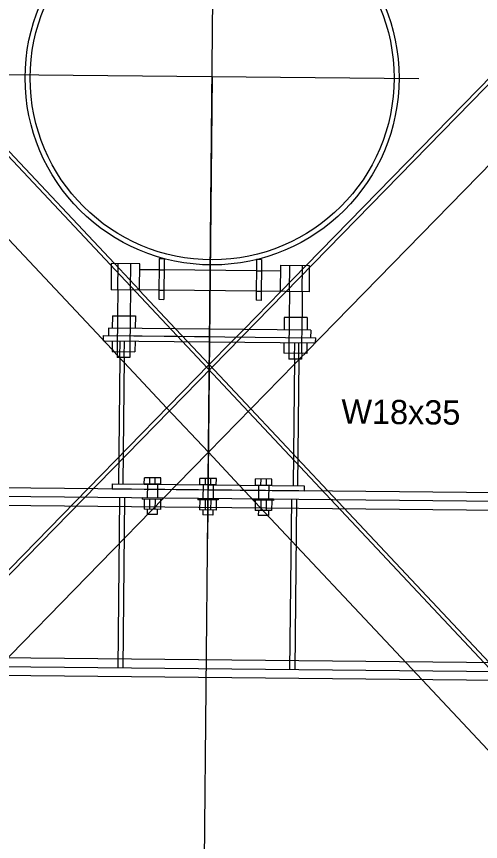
# Model space of a CAD drawing. Extents: x 632312 to 632425, y 378332 to 378413.
# Drawn here: x 632344.74 to 632348.57, y 378386.07 to 378392.88 of the extents above; entities that cross this region are included whole.
import ezdxf

# ---------------------------------------------------------------- set-up
doc = ezdxf.new("R2010")
doc.units = 0
for name, color, linetype in [('B_Boring', 7, 'Continuous'), ('R_Proposed Const Limits Cut', 7, 'Continuous'), ('R_Road Edge of Shoulder', 7, 'Continuous'), ('SHT_Dimensions', 7, 'Continuous')]:
    doc.layers.add(name, color=color, linetype=linetype)

msp = doc.modelspace()

# ---------------------------------------------------------------- linework, layer by layer
at = {"layer": 'B_Boring'}
for p, q in [((632345.9195, 378390.881), (632345.9162, 378390.5452)), ((632345.9195, 378390.881), (632345.9606, 378390.8806)), ((632345.9606, 378390.8806), (632345.9573, 378390.5448)), ((632346.7211, 378390.873), (632346.7178, 378390.5372)), ((632346.7622, 378390.8726), (632346.7211, 378390.873)), ((632346.7622, 378390.8726), (632346.7588, 378390.5368)), ((632345.5242, 378390.8408), (632345.522, 378390.624)), ((632345.7583, 378390.8385), (632345.5242, 378390.8408)), ((632345.7561, 378390.6217), (632345.7583, 378390.8385)), ((632345.9186, 378390.7881), (632345.7578, 378390.7897)), ((632346.7202, 378390.7801), (632345.9597, 378390.7877)), ((632346.922, 378390.7781), (632346.7612, 378390.7797)), ((632346.9204, 378390.6101), (632346.9225, 378390.8269)), ((632346.9225, 378390.8269), (632347.1566, 378390.8246)), ((632347.1566, 378390.8246), (632347.1545, 378390.6078)), ((632345.9169, 378390.6201), (632345.522, 378390.624)), ((632345.5776, 378390.6235), (632345.5754, 378390.41)), ((632345.6824, 378390.6224), (632345.6802, 378390.4089)), ((632346.7185, 378390.6121), (632345.958, 378390.6197)), ((632347.1545, 378390.6078), (632346.7596, 378390.6117)), ((632346.9942, 378390.6094), (632346.992, 378390.3959)), ((632347.0989, 378390.6083), (632347.0968, 378390.3949)), ((632345.9162, 378390.5452), (632345.9573, 378390.5448)), ((632346.7588, 378390.5368), (632346.7178, 378390.5372)), ((632345.5332, 378390.4104), (632345.5322, 378390.3083)), ((632345.5332, 378390.4104), (632345.7224, 378390.4085)), ((632345.7224, 378390.4085), (632345.7214, 378390.3064)), ((632346.9498, 378390.3963), (632346.9488, 378390.2942)), ((632347.139, 378390.3944), (632346.9498, 378390.3963)), ((632347.139, 378390.3944), (632347.138, 378390.2923)), ((632345.5018, 378390.3086), (632345.5012, 378390.2454)), ((632347.1684, 378390.292), (632345.5018, 378390.3086)), ((632345.4591, 378390.2041), (632345.4595, 378390.2458)), ((632345.4595, 378390.2458), (632347.2094, 378390.2284)), ((632347.1684, 378390.292), (632347.1678, 378390.2288)), ((632345.4591, 378390.2041), (632347.209, 378390.1867)), ((632345.5312, 378390.2034), (632345.5303, 378390.1154)), ((632345.7204, 378390.2015), (632345.7195, 378390.1135)), ((632346.9478, 378390.1893), (632346.9469, 378390.1013)), ((632347.137, 378390.1874), (632347.1361, 378390.0994)), ((632347.209, 378390.1867), (632347.2094, 378390.2284)), ((632345.5303, 378390.1154), (632345.7195, 378390.1135)), ((632345.5725, 378390.115), (632345.572, 378390.0659)), ((632345.6773, 378390.1139), (632345.6768, 378390.0649)), ((632347.1361, 378390.0994), (632346.9469, 378390.1013)), ((632346.9891, 378390.1009), (632346.9886, 378390.0519)), ((632347.0939, 378390.0998), (632347.0934, 378390.0508)), ((632345.6768, 378390.0649), (632345.572, 378390.0659)), ((632345.5952, 378390.0657), (632345.5849, 378389.0232)), ((632345.6307, 378390.0654), (632345.6203, 378389.0228)), ((632347.0934, 378390.0508), (632346.9886, 378390.0519)), ((632347.0348, 378390.0514), (632347.0244, 378389.0089)), ((632347.0702, 378390.051), (632347.0598, 378389.0085)), ((632345.7963, 378389.0211), (632345.7969, 378389.0732)), ((632345.9322, 378389.0718), (632345.7969, 378389.0732)), ((632345.8415, 378389.0206), (632345.842, 378389.0727)), ((632351.8217, 378388.9195), (632340.8222, 378389.0289)), ((632345.5307, 378389.0237), (632345.5303, 378388.982)), ((632345.5307, 378389.0237), (632347.114, 378389.008)), ((632345.9317, 378389.0197), (632345.7963, 378389.0211)), ((632345.8224, 378389.0208), (632345.8212, 378388.9067)), ((632345.8866, 378389.0202), (632345.8871, 378389.0723)), ((632345.9057, 378389.02), (632345.9046, 378388.9058)), ((632345.9317, 378389.0197), (632345.9322, 378389.0718)), ((632346.2546, 378389.0165), (632346.2552, 378389.0686)), ((632346.39, 378389.0152), (632346.2546, 378389.0165)), ((632346.3906, 378389.0673), (632346.2552, 378389.0686)), ((632346.2807, 378389.0163), (632346.2795, 378388.9021)), ((632346.2998, 378389.0161), (632346.3003, 378389.0682)), ((632346.3449, 378389.0156), (632346.3454, 378389.0677)), ((632346.364, 378389.0155), (632346.3629, 378388.9013)), ((632346.39, 378389.0152), (632346.3906, 378389.0673)), ((632346.713, 378389.012), (632346.7135, 378389.0641)), ((632346.8484, 378389.0106), (632346.713, 378389.012)), ((632346.8489, 378389.0627), (632346.7135, 378389.0641)), ((632346.739, 378389.0117), (632346.7379, 378388.8976)), ((632346.7581, 378389.0115), (632346.7586, 378389.0636)), ((632346.8032, 378389.0111), (632346.8037, 378389.0632)), ((632346.8223, 378389.0109), (632346.8212, 378388.8967)), ((632346.8484, 378389.0106), (632346.8489, 378389.0627)), ((632347.114, 378389.008), (632347.1135, 378388.9663)), ((632351.8209, 378388.847), (632340.8215, 378388.9564)), ((632345.5303, 378388.9821), (632347.1135, 378388.9663)), ((632345.5921, 378388.909), (632345.5781, 378387.504)), ((632345.6337, 378388.9085), (632345.6198, 378387.5036)), ((632345.7796, 378388.9071), (632345.7795, 378388.8967)), ((632345.9461, 378388.895), (632345.7795, 378388.8967)), ((632345.9462, 378388.9054), (632345.7796, 378388.9071)), ((632345.7951, 378388.8965), (632345.7943, 378388.8132)), ((632345.8402, 378388.8961), (632345.8394, 378388.8127)), ((632345.8854, 378388.8956), (632345.8845, 378388.8123)), ((632345.9305, 378388.8952), (632345.9297, 378388.8118)), ((632345.9462, 378388.9054), (632345.9461, 378388.895)), ((632346.2379, 378388.9025), (632346.2378, 378388.8921)), ((632346.4044, 378388.8905), (632346.2378, 378388.8921)), ((632346.4045, 378388.9009), (632346.2379, 378388.9025)), ((632346.2534, 378388.892), (632346.2526, 378388.8086)), ((632346.2985, 378388.8915), (632346.2977, 378388.8082)), ((632346.3437, 378388.8911), (632346.3428, 378388.8077)), ((632346.3888, 378388.8906), (632346.388, 378388.8073)), ((632346.4045, 378388.9009), (632346.4044, 378388.8905)), ((632346.6962, 378388.898), (632346.6961, 378388.8876)), ((632346.8627, 378388.8859), (632346.6961, 378388.8876)), ((632346.8628, 378388.8963), (632346.6962, 378388.898)), ((632346.7117, 378388.8874), (632346.7109, 378388.8041)), ((632346.7568, 378388.887), (632346.756, 378388.8036)), ((632346.802, 378388.8865), (632346.8012, 378388.8032)), ((632346.8471, 378388.8861), (632346.8463, 378388.8027)), ((632346.8628, 378388.8963), (632346.8627, 378388.8859)), ((632347.0087, 378388.8949), (632346.9947, 378387.4899)), ((632347.0503, 378388.8945), (632347.0364, 378387.4895)), ((632345.9297, 378388.8118), (632345.7943, 378388.8132)), ((632345.8203, 378388.8129), (632345.8199, 378388.7713)), ((632345.9036, 378388.8121), (632345.9032, 378388.7704)), ((632346.388, 378388.8073), (632346.2526, 378388.8086)), ((632346.2786, 378388.8084), (632346.2782, 378388.7667)), ((632346.3619, 378388.8075), (632346.3615, 378388.7659)), ((632346.8463, 378388.8027), (632346.7109, 378388.8041)), ((632346.7369, 378388.8038), (632346.7365, 378388.7622)), ((632346.8203, 378388.803), (632346.8198, 378388.7613)), ((632345.9032, 378388.7704), (632345.8199, 378388.7713)), ((632346.3615, 378388.7659), (632346.2782, 378388.7667)), ((632346.8198, 378388.7613), (632346.7365, 378388.7622)), ((632351.807, 378387.4421), (632340.8075, 378387.5515)), ((632351.8062, 378387.3696), (632340.8068, 378387.479))]:
    msp.add_line(p, q, dxfattribs=at)
for points in [[(632347.1362, 378390.1143), (632350.9136, 378393.9818), (632350.5559, 378394.3312), (632347.1313, 378390.8248)], [(632344.6417, 378391.8078), (632345.5495, 378390.8406)], [(632345.5305, 378390.1302), (632344.6345, 378391.0849)], [(632345.7549, 378390.6217), (632346.054, 378390.3031)], [(632346.9216, 378390.6101), (632346.6163, 378390.2975)], [(632346.5148, 378390.1936), (632346.3322, 378390.0067), (632345.3334, 378388.984)], [(632346.1533, 378390.1972), (632346.3322, 378390.0067)], [(632345.5722, 378390.0858), (632345.5446, 378390.1152)], [(632347.0936, 378390.0706), (632347.1218, 378390.0995)], [(632345.5952, 378390.0613), (632345.591, 378390.0657)], [(632347.0701, 378390.0466), (632347.0744, 378390.051)], [(632345.9825, 378389.6486), (632345.6302, 378390.0239)], [(632346.0659, 378389.0184), (632346.325, 378389.2837), (632347.0343, 378390.01)], [(632346.6747, 378389.6417), (632347.3104, 378388.9644)], [(632346.5788, 378389.0133), (632346.325, 378389.2837)], [(632350.4619, 378384.876), (632348.0868, 378387.4066)]]:
    msp.add_lwpolyline(points, dxfattribs=at)
for radius in [1.5417, 1.5]:
    msp.add_circle((632346.3557, 378392.3708), radius, dxfattribs=at)
at = {"layer": 'R_Proposed Const Limits Cut'}
for p, q in [((632342.1725, 378394.3929), (632350.8037, 378385.1968)), ((632350.5783, 378394.3094), (632341.7659, 378385.2867)), ((632345.7561, 378390.6217), (632345.5495, 378390.8406)), ((632345.5776, 378390.6235), (632345.5797, 378390.8403)), ((632345.6824, 378390.6224), (632345.6845, 378390.8392)), ((632345.9186, 378390.7881), (632345.9597, 378390.7877)), ((632346.7202, 378390.7801), (632346.7612, 378390.7797)), ((632346.9216, 378390.6101), (632347.1313, 378390.8248)), ((632346.9942, 378390.6094), (632346.9963, 378390.8262)), ((632347.0989, 378390.6083), (632347.1011, 378390.8251)), ((632345.9169, 378390.6201), (632345.958, 378390.6197)), ((632346.7185, 378390.6121), (632346.7596, 378390.6117)), ((632345.5754, 378390.41), (632345.5725, 378390.115)), ((632345.6802, 378390.4089), (632345.6773, 378390.1139)), ((632346.992, 378390.3959), (632346.9891, 378390.1009)), ((632347.0939, 378390.0998), (632347.0968, 378390.3949)), ((632346.1533, 378390.1972), (632346.054, 378390.3031)), ((632346.5148, 378390.1936), (632346.6163, 378390.2975)), ((632345.5952, 378390.0657), (632345.5966, 378390.2028)), ((632345.6307, 378390.0654), (632345.632, 378390.2024)), ((632347.0348, 378390.0514), (632347.0361, 378390.1884)), ((632347.0702, 378390.051), (632347.0715, 378390.1881)), ((632345.5305, 378390.1302), (632345.5446, 378390.1152)), ((632347.1218, 378390.0995), (632347.1362, 378390.1143)), ((632345.5722, 378390.0858), (632345.591, 378390.0657)), ((632345.5952, 378390.0613), (632345.6302, 378390.0239)), ((632347.0343, 378390.01), (632347.0701, 378390.0466)), ((632347.0744, 378390.051), (632347.0936, 378390.0706)), ((632346.6747, 378389.6417), (632346.3322, 378390.0067)), ((632345.9825, 378389.6486), (632346.325, 378389.2837)), ((632344.5262, 378387.442), (632346.0659, 378389.0184)), ((632346.5788, 378389.0133), (632348.0868, 378387.4066)), ((632345.3334, 378388.984), (632343.834, 378387.4489)), ((632347.3104, 378388.9644), (632348.779, 378387.3997)), ((632351.8202, 378388.7737), (632340.8208, 378388.8831)), ((632351.8077, 378387.5154), (632340.8082, 378387.6248))]:
    msp.add_line(p, q, dxfattribs=at)
at = {"layer": 'R_Road Edge of Shoulder'}
msp.add_line((632346.2256, 378379.2847), (632346.5561, 378412.5263), dxfattribs=at)
at = {"layer": 'SHT_Dimensions'}
for p, q in [((632344.6401, 378392.3999), (632348.0606, 378392.3659)), ((632346.3558, 378392.3828), (632346.3179, 378388.5712)), ((632346.3345, 378390.2371), (632345.5012, 378390.2454))]:
    msp.add_line(p, q, dxfattribs=at)

# ---------------------------------------------------------------- texts
msp.add_text('W18x35', height=0.2, rotation=359.43036, dxfattribs=at).set_placement((632347.4205, 378389.5205))

doc.saveas('drawing.dxf')
